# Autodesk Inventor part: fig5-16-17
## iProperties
Created: 2004-05
Part Number: fig5-16-17
Document SubType Name: Modeling
Designer: CADCIM Technologies
Manufacturer: Standard
Standards Organization: Custom
Author: CADCIM Technologies
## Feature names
1. Extrusion1
2. Extrusion2
3. Fillet1
